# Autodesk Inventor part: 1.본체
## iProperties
Created: 2014-12
Part Number: 1.본체
Document SubType Name: Modeling
Designer: Administrator
Density: 2.71 g/cm^3
Material: 알루미늄-6061
Mass: 613.667 g
Surface Area: 665.119 cm^2
Volume: 226.445 cm^3
Author: Administrator
